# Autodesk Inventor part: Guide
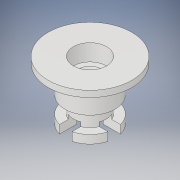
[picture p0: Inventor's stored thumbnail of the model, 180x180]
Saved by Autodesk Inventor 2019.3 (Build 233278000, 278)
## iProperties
Created: 2018-06
Part Number: Guide
Material: Plastique ABS
Document SubType Name: Modeling
Designer: Fabian Perrée
Density: 1.06 g/cm^3
Appearance: Lisse - Blanc
Author: Fabian Perrée
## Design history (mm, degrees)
sketch "Esquisse1"
  geometry: L1 (0, 0)-(0, 14); L2 (0, 14)-(10, 14); L3 (10, 14)-(10, 12.5); L4 (10, 12.5)-(6, 12.5); L5 (6, 12.5)-(6, 6); L6 (6, 6)-(4, 6); L7 (4, 6)-(4, 2); L8 (4, 2)-(6, 2); L9 (6, 2)-(6, 0); L10 (6, 0)-(0, 0); L11 (4, 14)-(4, 10); L12 (4, 10)-(2.25, 10); L13 (2.25, 10)-(2.25, 3); L14 (2.25, 3)-(0, 3)
  constraints: 28 end point, 12 perpendicular, 2 point on line, 2 vertical, 1 collinear
  dimensions: "d0" = 14 distance of L1.start L1.end; "d2" = 1.5 distance of L2.end L3.end; "d3" = 20 diameter of L3 L1; "d5" = 12 diameter of L5 L1; "d6" = 8 diameter of L7 L1; "d7" = 6.5 distance of L4.end L5.end; "d8" = 4 distance of L6.end L7.end; "d9" = 2 distance of L8.end L9.end (derived); "d10" = 8 diameter of L11 L1; "d11" = 4.5 diameter of L13 L1; "d12" = 4 distance of L11.start L11.end; "d13" = 3 distance between parallel lines of L10 L14
revolve "Révolution1" sketch "Esquisse1" stored, may be unused: angle "d14" = 90 deg
sketch "Esquisse2"
  geometry: L1 (6, 1.5)-(0, 1.5); L2 (0, 1.5)-(0, -1.5); L3 (0, -1.5)-(6, -1.5); L4 (6, -1.5)-(6, 1.5); L5 (0, 0)-(10, 0); C1 r 6 at (0, 0) reference; 1 further point
  constraints: 10 end point, 2 parallel, 1 horizontal, 1 horizontal alignment, 1 midpoint, 1 perpendicular, 1 tangent, 2 other
  dimensions: "d15" = 3 distance of L3.end L1.start
extrude "Extrusion1" cut sketch "Esquisse2" distance "d16" = 3; taper "d17" = 0 deg
pattern_circular "Réseau circulaire1" dims angle "d19" = 360 deg
chamfer "Chanfrein1" distance "d21" = 0.5; stored, may be unused: second distance "d22" = 2, angle "d23" = 45 deg
sketch "Esquisse3"
  geometry: C1 r 2.25 at (0, 0); A1 r 2.25 centre (0, 0) between (-1.5, -1.677) and (1.5, -1.677) reference
  constraints: 1 centre point, 1 coincident, 1 concentric
extrude "Extrusion2" cut sketch "Esquisse3" extent not by distance; stored distance "d24" = 10; taper "d25" = 0 deg
node "Solide1"
